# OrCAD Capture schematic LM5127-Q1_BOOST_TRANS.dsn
size Custom; title: LM5127-Q1 2.2MHz Wide VIN Automotive Front-stage; rev: 1.0; note: Datasheet: NA     EVM: NA; note: Synchronous Step Down Converter
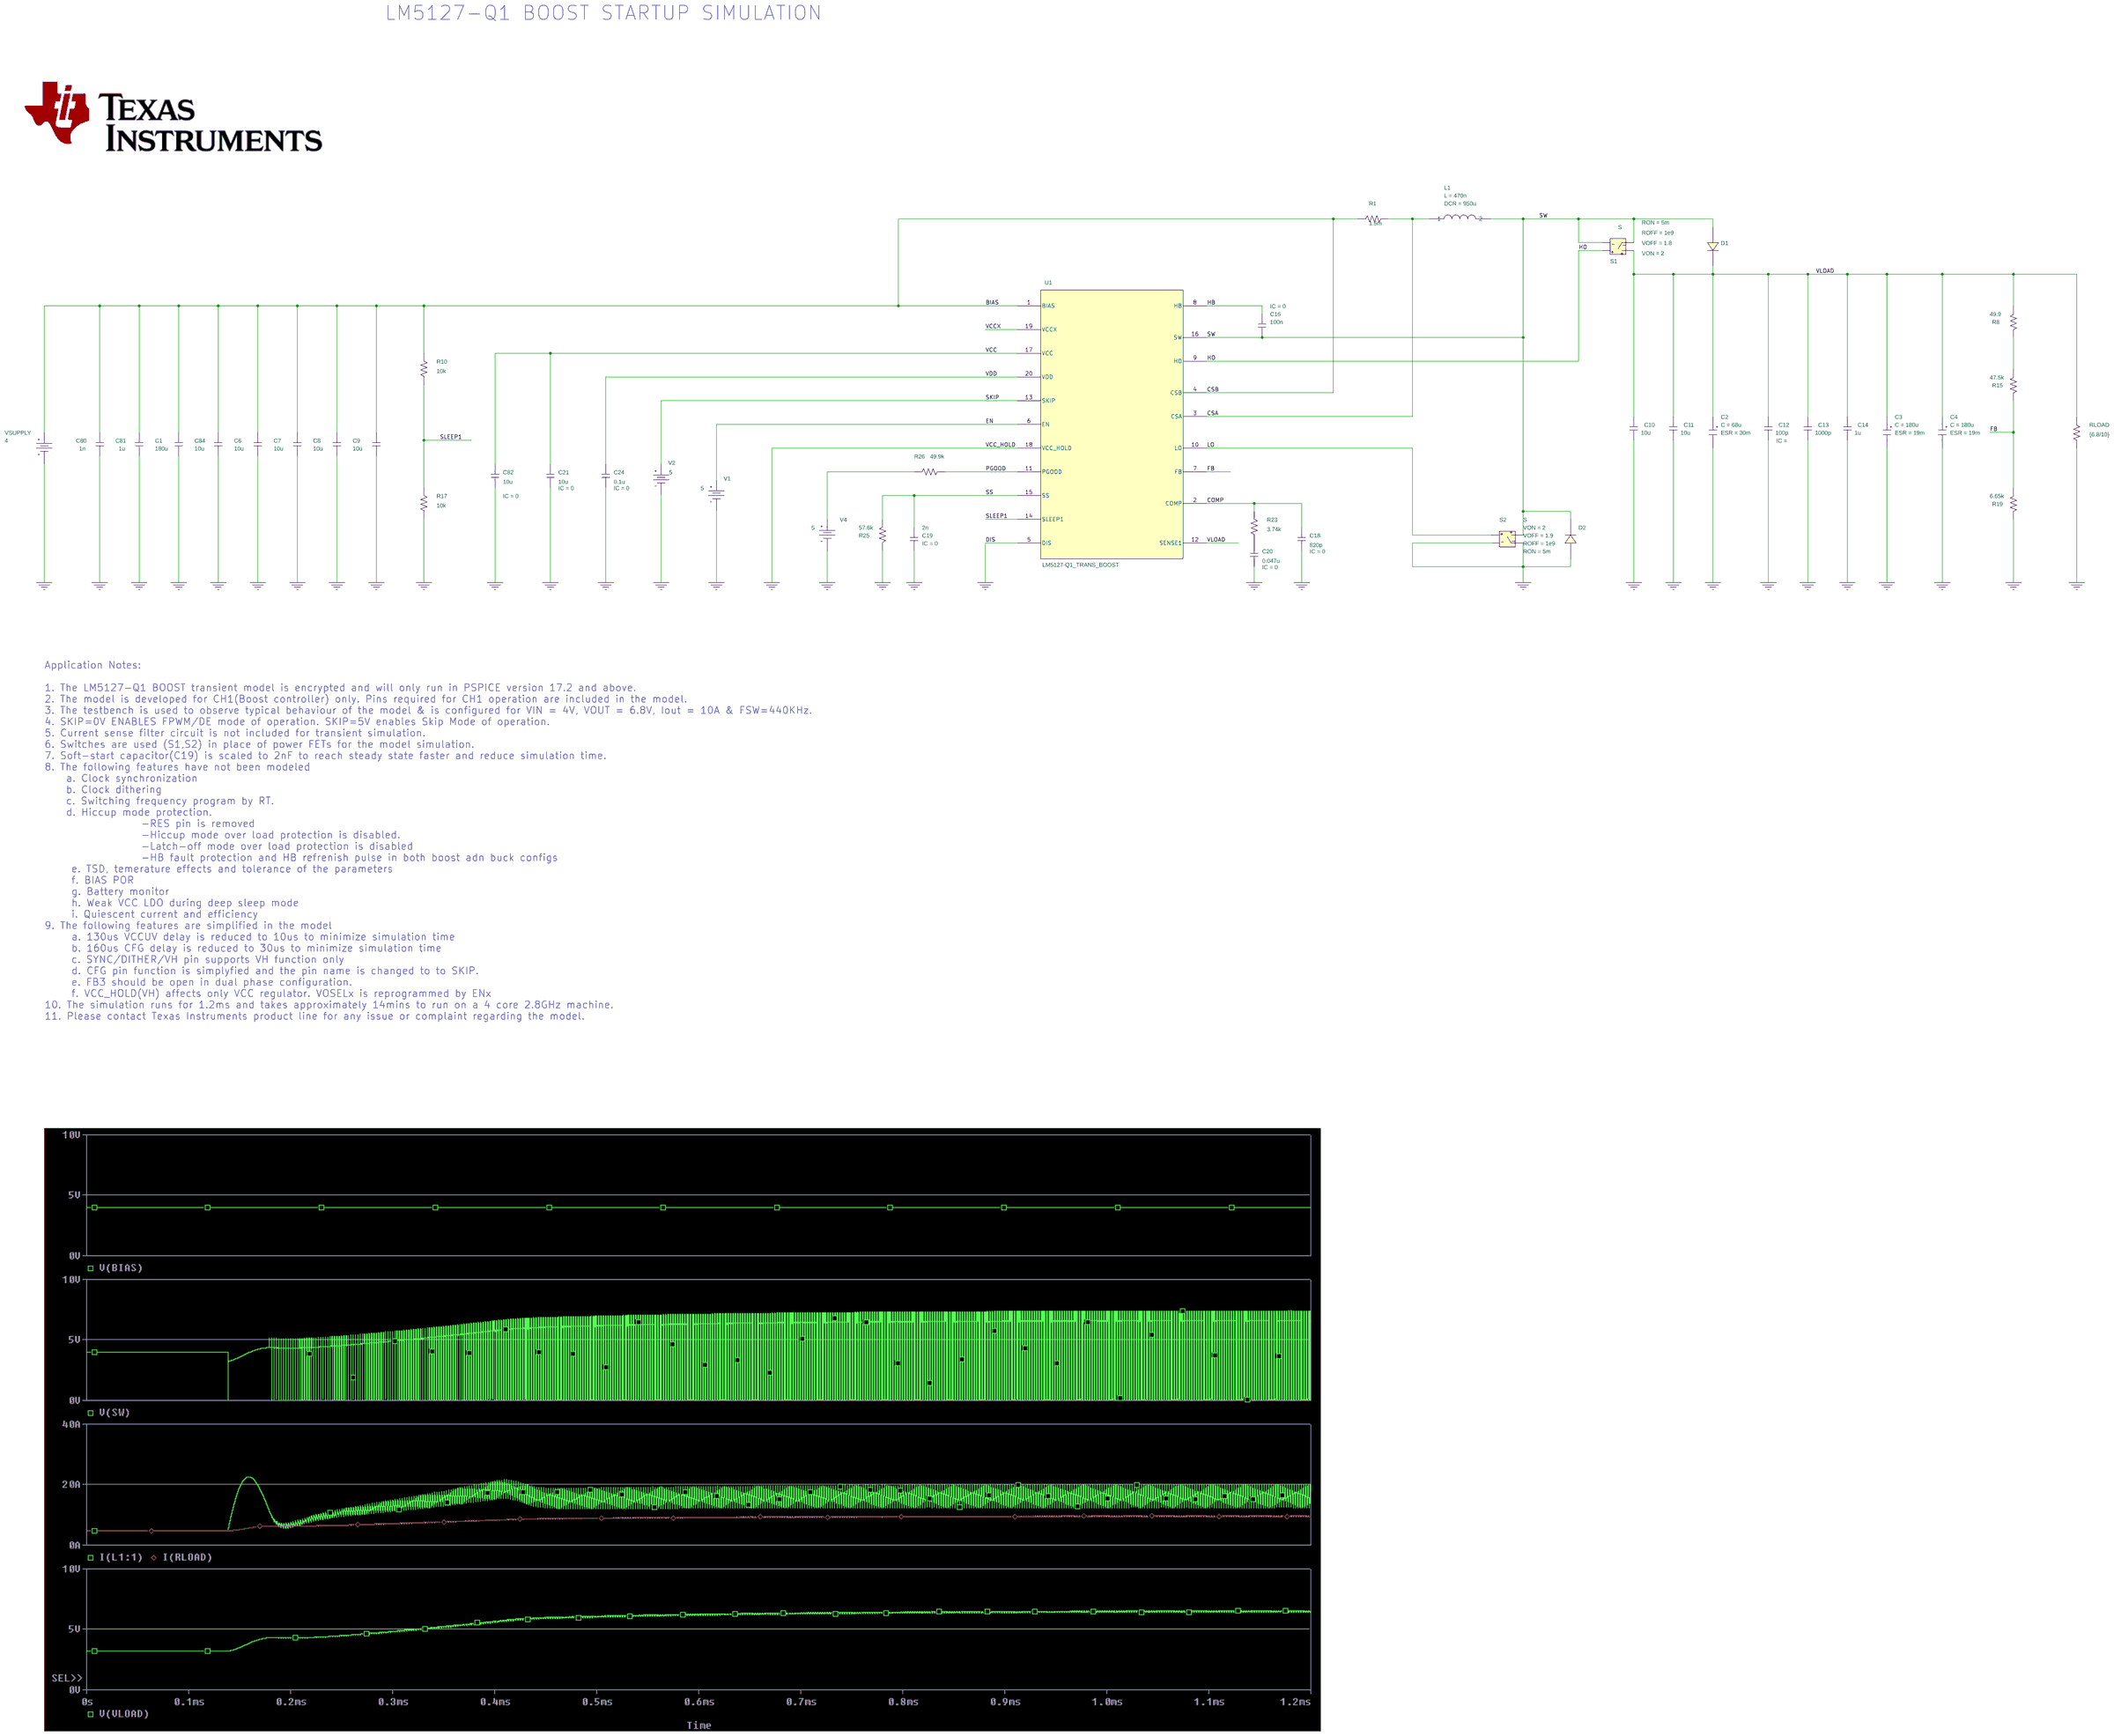
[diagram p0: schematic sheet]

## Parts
C1  180u  [RAD/CK05]
C2  CESR
C3  CESR
C4  CESR
C6  10u  [RAD/CK05]
C7  10u  [RAD/CK05]
C8  10u  [RAD/CK05]
C9  10u  [RAD/CK05]
C10  10u  [RAD/CK05]
C11  10u  [RAD/CK05]
C12  100p  [RAD/CK05]
C13  1000p  [RAD/CK05]
C14  1u  [RAD/CK05]
C16  100n  [RAD/CK05]
C18  820p  [RAD/CK05]
C19  2n  [RAD/CK05]
C20  0.047u  [RAD/CK05]
C21  10u  [RAD/CK05]
C24  0.1u  [RAD/CK05]
C80  1n  [RAD/CK05]
C81  1u  [RAD/CK05]
C82  10u  [RAD/CK05]
C84  10u  [RAD/CK05]
D1  D_D1
D2  D_D1
L1  LDCR
R1  1.5m  [AX/RC05]
R8  49.9  [AX/RC05]
R10  10k  [AX/RC05]
R15  47.5k  [AX/RC05]
R17  10k  [AX/RC05]
R19  6.65k  [AX/RC05]
R23  3.74k  [AX/RC05]
R25  57.6k  [AX/RC05]
R26  49.9k  [AX/RC05]
RLOAD  {6.8/10}  [AX/RC05]
S1  S
S2  S
U1  LM5127-Q1_TRANS_BOOST
V1  VDC
V2  VDC
V4  VDC
VSUPPLY  VDC

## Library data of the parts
C1 C6-C14 C80 C81 C84 = C
C2 = CESR_0: C: 68u; ESR: 30m; PSpiceTemplate: X^@REFDES %IN %OUT @MODEL PARAMS:  ?C|C=@C||C=100u|  ?ESR|ESR=@ESR||ESR=0.01|; X: 1
C3 C4 = CESR_0: C: 180u; ESR: 19m; PSpiceTemplate: X^@REFDES %IN %OUT @MODEL PARAMS:  ?C|C=@C||C=100u|  ?ESR|ESR=@ESR||ESR=0.01|; X: 1
C16 C18-C21 C24 C82 = C: IC: 0
D1 D2 = D_D1
L1 = LDCR: DCR: 950u; L: 470n
R1 R8 R10 R15 R17 R19 R23 R25 R26 RLOAD = R
S1 = S: ROFF: 1e9; RON: 5m; VOFF: 1.8; VON: 2
S2 = S: ROFF: 1e9; RON: 5m; VOFF: 1.9; VON: 2
U1 = LM5127-Q1_TRANS_BOOST
V1 V2 V4 = VDC: DC: 5
VSUPPLY = VDC: DC: 4

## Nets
VCC: C21.2 C82.2 U1.17(VCC)
VCCX: U1.19(VCCX)
VDD: C24.2 U1.20(VDD)
0: C1.2 C2.2(OUT) C3.2(OUT) C4.2(OUT) C6.2 C7.2 C8.2 C9.2 C10.2 C11.2 C12.2 C13.2 C14.2 C18.1 C19.1 C20.1 C21.1 C24.1 C80.2 C81.2 C82.1 C84.2 D2.2(A) R17.1 R19.2 R25.1 RLOAD.2 S2.1(2) S2.3(4) U1.5(DIS) U1.18(VCC_HOLD) V1.1(-) V2.1(-) V4.1(-) VSUPPLY.1(-)
BIAS: C1.1 C6.1 C7.1 C8.1 C9.1 C80.1 C81.1 C84.1 R1.1 R10.2 U1.1(BIAS) U1.4(CSB) VSUPPLY.0(+)
COMP: C18.2 R23.2 U1.2(COMP)
CSA: L1.1 R1.2 U1.3(CSA)
EN: U1.6(EN) V1.0(+)
FB: R15.2 R19.1 U1.7(FB)
HB: C16.2 U1.8(HB)
HO: S1.0(1) U1.9(HO)
LO: S2.0(1) U1.10(LO)
PGOOD: R26.1 U1.11(PGOOD)
SKIP: U1.13(SKIP) V2.0(+)
SLEEP1: R10.1 R17.2 U1.14(SLEEP1)
SS: C19.2 R25.2 U1.15(SS)
SW: C16.1 D1.2(A) D2.1(C) L1.2 S1.1(2) S1.3(4) S2.2(3) U1.16(SW)
VLOAD: C2.1(IN) C3.1(IN) C4.1(IN) C10.1 C11.1 C12.1 C13.1 C14.1 D1.1(C) R8.1 RLOAD.1 S1.2(3) U1.12(SENSE1)
N16783640: R26.2 V4.0(+)
N16793214: R8.2 R15.1
N16794881: C20.2 R23.1

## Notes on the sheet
- LM5127-Q1 BOOST STARTUP SIMULATION
- Application Notes:
  1. The LM5127-Q1 BOOST transient model is encrypted and will only run in PSPICE version 17.2 and above.
  2. The model is developed for CH1(Boost controller) only. Pins required for CH1 operation are included in the model.
  3. The testbench is used to observe typical behaviour of the model & is configured for VIN = 4V, VOUT = 6.8V, Iout = 10A & FSW=440KHz.
  4. SKIP=0V ENABLES FPWM/DE mode of operation. SKIP=5V enables Skip Mode of operation.
  5. Current sense filter circuit is not included for transient simulation.
  6. Switches are used (S1,S2) in place of power FETs for the model simulation.
  7. Soft-start capacitor(C19) is scaled to 2nF to reach steady state faster and reduce simulation time.
  8. The following features have not been modeled
      a. Clock synchronization
      b. Clock dithering
      c. Switching frequency program by RT.
      d. Hiccup mode protection.
                    -RES pin is removed
                    -Hiccup mode over load protection is disabled.
                    -Latch-off mode over load protection is disabled
                    -HB fault protection and HB refrenish pulse in both boost adn buck configs
       e. TSD, temerature effects and tolerance of the parameters
       f. BIAS POR
       g. Battery monitor
       h. Weak VCC LDO during deep sleep mode
       i. Quiescent current and efficiency
  9. The following features are simplified in the model
       a. 130us VCCUV delay is reduced to 10us to minimize simulation time
       b. 160us CFG delay is reduced to 30us to minimize simulation time
       c. SYNC/DITHER/VH pin supports VH function only
       d. CFG pin function is simplyfied and the pin name is changed to to SKIP.
       e. FB3 should be open in dual phase configuration.
       f. VCC_HOLD(VH) affects only VCC regulator. VOSELx is reprogrammed by ENx
  10. The simulation runs for 1.2ms and takes approximately 14mins to run on a 4 core 2.8GHz machine.
  11. Please contact Texas Instruments product line for any issue or complaint regarding the model.
